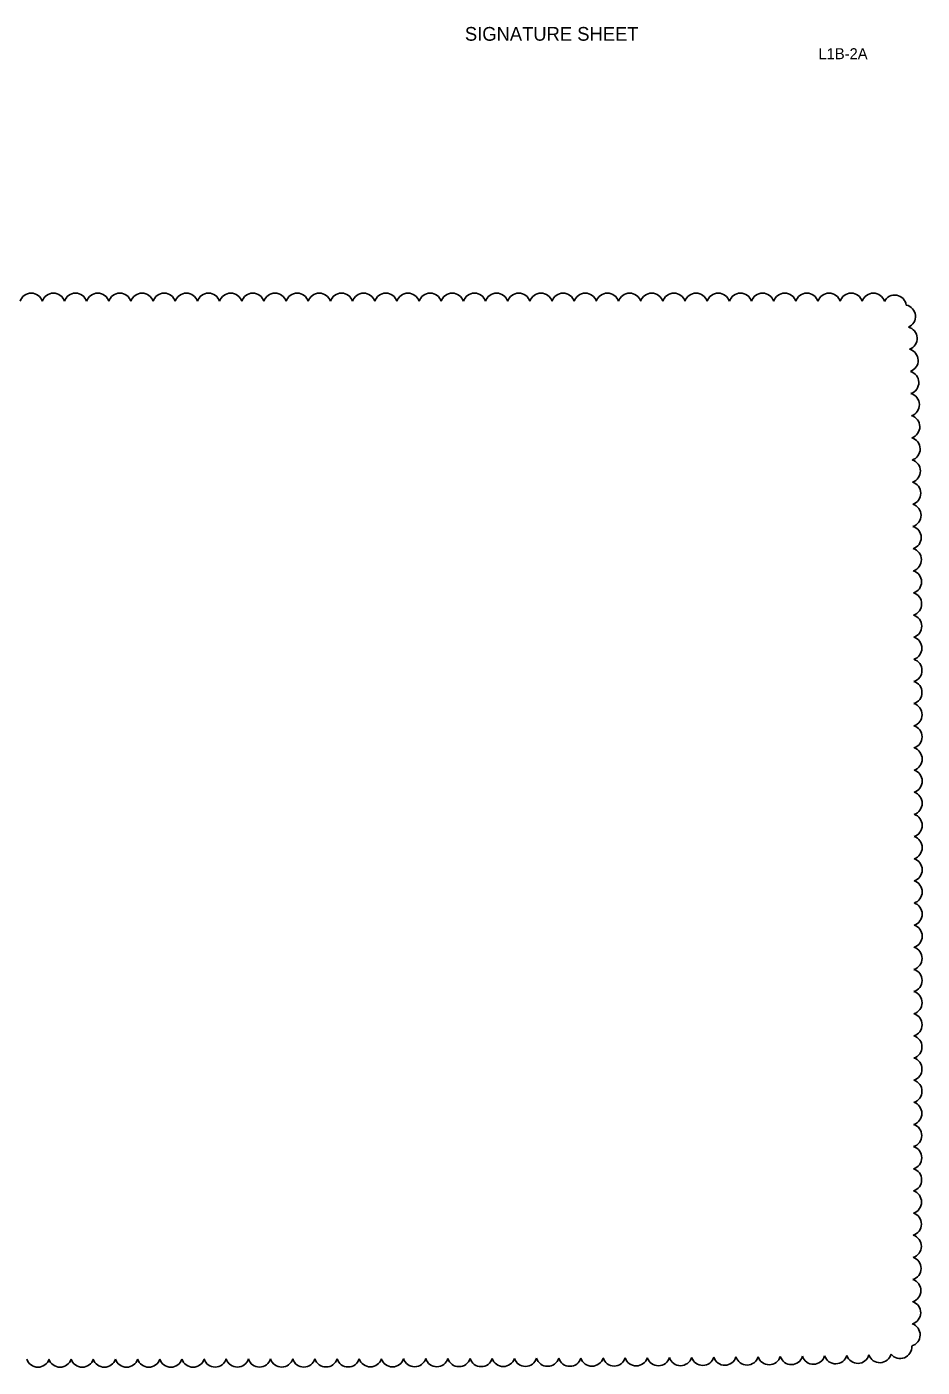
# Model space of a CAD drawing. Extents: x -811.2 to -795, y -2295.2 to -2235.1.
# Drawn here: x -803.18 to -795.04, y -2269.67 to -2257.47 of the extents above; entities that cross this region are included whole.
import ezdxf

# ---------------------------------------------------------------- set-up
doc = ezdxf.new("R2010")
doc.units = 0
for name, color, linetype in [('Cloud_dp', 7, 'Continuous'), ('PlotBorder_dp', 7, 'Continuous'), ('SheetLines_dp', 7, 'Continuous')]:
    doc.layers.add(name, color=color, linetype=linetype)

msp = doc.modelspace()

# ---------------------------------------------------------------- linework, layer by layer
at = {"layer": 'Cloud_dp'}
for centre, start, end in [((-803.143, -2260.002), 17.5, 162.5), ((-802.941, -2260.002), 17.5, 162.5), ((-802.74, -2260.002), 17.5, 162.5), ((-802.538, -2260.002), 17.5, 162.5), ((-802.337, -2260.002), 17.5, 162.5), ((-802.135, -2260.002), 17.5, 162.5), ((-801.934, -2260.002), 17.5, 162.5), ((-801.732, -2260.002), 17.5, 162.5), ((-801.531, -2260.002), 17.5, 162.5), ((-801.329, -2260.002), 17.5, 162.5), ((-801.128, -2260.002), 17.5, 162.5), ((-800.926, -2260.002), 17.5, 162.5), ((-800.724, -2260.002), 17.5, 162.5), ((-800.523, -2260.002), 17.5, 162.5), ((-800.321, -2260.002), 17.5, 162.5), ((-800.12, -2260.002), 17.5, 162.5), ((-799.918, -2260.002), 17.5, 162.5), ((-799.717, -2260.002), 17.5, 162.5), ((-799.515, -2260.002), 17.5, 162.5), ((-799.314, -2260.002), 17.5, 162.5), ((-799.112, -2260.002), 17.5, 162.5), ((-798.911, -2260.002), 17.5, 162.5), ((-798.709, -2260.002), 17.5, 162.5), ((-798.507, -2260.002), 17.5, 162.5), ((-798.306, -2260.002), 17.5, 162.5), ((-798.104, -2260.002), 17.5, 162.5), ((-797.903, -2260.002), 17.5, 162.5), ((-797.701, -2260.002), 17.5, 162.5), ((-797.5, -2260.002), 17.5, 162.5), ((-797.298, -2260.002), 17.5, 162.5), ((-797.097, -2260.002), 17.5, 162.5), ((-796.895, -2260.002), 17.5, 162.5), ((-796.693, -2260.002), 17.5, 162.5), ((-796.492, -2260.002), 17.5, 162.5), ((-796.29, -2260.002), 17.5, 162.5), ((-796.089, -2260.002), 17.5, 162.5), ((-795.887, -2260.002), 17.5, 162.5), ((-795.686, -2260.002), 17.5, 162.5), ((-795.484, -2260.002), 17.5, 162.5), ((-795.29, -2260.019), 7.7061, 152.7061), ((-795.207, -2260.108), 293.1451, 78.1451), ((-795.192, -2260.307), 290.3535, 75.3535), ((-795.183, -2260.508), 289.5186, 74.5186), ((-795.177, -2260.71), 289.0656, 74.0656), ((-795.172, -2260.911), 288.7699, 73.7699), ((-795.168, -2261.112), 288.5573, 73.5573), ((-795.165, -2261.314), 288.3949, 73.3949), ((-795.162, -2261.515), 288.2656, 73.2656), ((-795.159, -2261.717), 288.1595, 73.1595), ((-795.157, -2261.918), 288.0704, 73.0704), ((-795.155, -2262.12), 287.9942, 72.9942), ((-795.153, -2262.321), 287.928, 72.928), ((-795.152, -2262.523), 287.8698, 72.8698), ((-795.151, -2262.724), 287.8182, 72.8182), ((-795.15, -2262.926), 287.772, 72.772), ((-795.149, -2263.127), 287.7302, 72.7302), ((-795.148, -2263.329), 287.6923, 72.6923), ((-795.148, -2263.53), 287.6577, 72.6577), ((-795.147, -2263.732), 287.6259, 72.6259), ((-795.147, -2263.933), 287.5965, 72.5965), ((-795.146, -2264.135), 287.5693, 72.5693), ((-795.146, -2264.336), 287.544, 72.544), ((-795.146, -2264.538), 287.5204, 72.5204), ((-795.146, -2264.739), 287.5008, 72.5008), ((-795.146, -2264.941), 287.4924, 72.4924), ((-795.146, -2265.143), 287.4849, 72.4849), ((-795.146, -2265.344), 287.4769, 72.4769), ((-795.146, -2265.546), 287.4682, 72.4682), ((-795.146, -2265.747), 287.4589, 72.4589), ((-795.147, -2265.949), 287.4488, 72.4488), ((-795.147, -2266.15), 287.4378, 72.4378), ((-795.147, -2266.352), 287.4258, 72.4258), ((-795.147, -2266.553), 287.4126, 72.4126), ((-795.148, -2266.755), 287.398, 72.398), ((-795.148, -2266.956), 287.3817, 72.3817), ((-795.148, -2267.158), 287.3633, 72.3633), ((-795.149, -2267.359), 287.3425, 72.3425), ((-795.15, -2267.561), 287.3185, 72.3185), ((-795.15, -2267.763), 287.2905, 72.2905), ((-795.151, -2267.964), 287.2573, 72.2573), ((-795.152, -2268.166), 287.217, 72.217), ((-795.153, -2268.367), 287.1666, 72.1666), ((-795.154, -2268.569), 287.101, 72.101), ((-795.156, -2268.77), 287.0106, 72.0106), ((-795.158, -2268.972), 286.8744, 71.8744), ((-795.16, -2269.173), 286.6317, 71.6317), ((-795.165, -2269.374), 285.9387, 70.9387), ((-795.241, -2269.484), 219.2472, 4.2472), ((-803.082, -2269.563), 197.4989, 342.4989), ((-802.881, -2269.563), 197.5044, 342.5044), ((-802.679, -2269.563), 197.5105, 342.5105), ((-802.478, -2269.563), 197.5167, 342.5167), ((-802.276, -2269.563), 197.5233, 342.5233), ((-802.074, -2269.563), 197.5301, 342.5301), ((-801.873, -2269.563), 197.5372, 342.5372), ((-801.671, -2269.563), 197.5447, 342.5447), ((-801.47, -2269.562), 197.5525, 342.5525), ((-801.268, -2269.562), 197.5607, 342.5607), ((-801.067, -2269.562), 197.5693, 342.5693), ((-800.865, -2269.562), 197.5784, 342.5784), ((-800.664, -2269.562), 197.5879, 342.5879), ((-800.462, -2269.561), 197.598, 342.598), ((-800.261, -2269.561), 197.6087, 342.6087), ((-800.059, -2269.56), 197.62, 342.62), ((-799.858, -2269.56), 197.6321, 342.6321), ((-799.656, -2269.559), 197.6449, 342.6449), ((-799.454, -2269.559), 197.6587, 342.6587), ((-799.253, -2269.558), 197.6734, 342.6734), ((-799.051, -2269.558), 197.6893, 342.6893), ((-798.85, -2269.557), 197.7064, 342.7064), ((-798.648, -2269.556), 197.725, 342.725), ((-798.447, -2269.555), 197.7453, 342.7453), ((-798.245, -2269.555), 197.7675, 342.7675), ((-798.044, -2269.554), 197.792, 342.792), ((-797.842, -2269.552), 197.8192, 342.8192), ((-797.641, -2269.551), 197.8496, 342.8496), ((-797.439, -2269.55), 197.8839, 342.8839), ((-797.238, -2269.549), 197.9231, 342.9231), ((-797.036, -2269.547), 197.9684, 342.9684), ((-796.835, -2269.545), 198.0216, 343.0216), ((-796.633, -2269.543), 198.0853, 343.0853), ((-796.432, -2269.541), 198.1633, 343.1633), ((-796.23, -2269.539), 198.2623, 343.2623), ((-796.029, -2269.536), 198.3936, 343.3936), ((-795.827, -2269.532), 198.5799, 343.5799), ((-795.626, -2269.528), 198.8753, 343.8753), ((-795.425, -2269.522), 199.4643, 344.4643)]:
    msp.add_arc(centre, 0.106, start, end, dxfattribs=at)

# ---------------------------------------------------------------- texts
at = {"layer": 'PlotBorder_dp'}
msp.add_text('       SIGNATURE SHEET         ', height=0.125, dxfattribs=at).set_placement((-799.524, -2257.599))
at = {"layer": 'SheetLines_dp'}
msp.add_text('L1B-2A ', height=0.1, dxfattribs=at).set_placement((-795.983, -2257.767))

doc.saveas('drawing.dxf')
